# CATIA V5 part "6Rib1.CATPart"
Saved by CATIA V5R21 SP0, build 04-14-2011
Part number: Rib1
Bounding box of the stored display mesh (mm): x 12 to 22, y -42.784 to 24.466, z 44.139 to 68.639
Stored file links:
  C:\Users\水心\Desktop\Arm_Detailed_Design_Assembly_Manu\6Rib1.CATPart
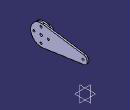
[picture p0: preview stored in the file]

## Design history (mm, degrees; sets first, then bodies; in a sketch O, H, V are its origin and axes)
Body1 (main body)
  DatumSurface1
  DatumSurface2
  Plane1 to Plane3: stored without definition
  Sketch1 on face of DatumSurface1, origin (22, 0, 0), H (0, 1, 0), V (0, 0, 1)
    projected circle E1 centre (-30.534, 56.389) radius 12.25 from edge of DatumSurface2
    projected arc E2 centre (-30.534, 56.389) radius 12.25 from (-28.7577, 68.5095) to (-28.7577, 44.2684) ccw from edge of DatumSurface2
    projected circle E3 centre (-30.534, 56.389) radius 1.5 from edge of DatumSurface2
    arc A1 centre (19.466, 56.389) radius 5 from (20.191, 51.4418) to (20.191, 61.3361) ccw
    point P1 (19.466, 56.389)
    reference intersected line E4 through (-30.534, 0) direction (0, 1) from Plane1
    line L1 (20.191, 61.3361) -> (-28.7577, 68.5095)
    axis line L2 (30.2795, 56.389) -> (-56.8378, 56.389)
    reference intersected line E5 through (0, 56.389) direction (1, 0) from Plane2
    line L3 (-28.7577, 44.2684) -> (20.191, 51.4418)
    point P4 (-28.7577, 44.2684)
    point P5 (-28.7577, 68.5095)
    point P8 (-28.7577, 68.5095)
    circle A2 centre (19.466, 56.389) radius 1.25
    circle A3 centre (-30.534, 64.889) radius 1.25
    point P9 (-30.534, 64.889)
    reference intersected line E6 through (0, 56.389) direction (-1, 0) from Plane3
    circle A4 centre (-39.034, 56.389) radius 1.25
    circle A5 centre (-30.534, 47.889) radius 1.25
    circle A6 centre (-22.034, 56.389) radius 1.25
    distance P1 E4 = 50
    radius A1 = 5
    radius A2 = 1.25
    radius A3 = 1.25
    distance E6 P9 = 8.5
    tangency: L1 E1, L1 A1, L3 A1, L3 E1
    horizontal: L2 H
    coincidence: P1 L2, L2 E5, E1 P4, E1 P5, L1 P8, P5 P8
  Pad1: profile Sketch1, direction (-1, 0, 0), length 2
Body2
  Sketch2 on end face of Pad1, origin (20, 0, 0), H (0, -1, 0), V (0, 0, 1)
    circle A1 centre (30.534, 56.389) radius 12.25
    point P1 (30.534, 56.389)
    reference projected arc E1 centre (30.534, 56.389) radius 12.25 from (28.7577, 44.2684) to (28.7577, 68.5095) ccw from edge [end face of Pad1 | face of Pad1 from Sketch1.E2]
    circle A2 centre (30.534, 64.889) radius 1.25
    point P2 (30.534, 64.889)
    circle A3 centre (39.034, 56.389) radius 1.25
    point P3 (39.034, 56.389)
    circle A4 centre (30.534, 47.889) radius 1.25
    point P4 (30.534, 47.889)
    circle A5 centre (22.034, 56.389) radius 1.25
    point P5 (22.034, 56.389)
    circle A6 centre (30.534, 56.389) radius 1.5
    radius A2 = 1.25
    radius A3 = 1.25
    radius A4 = 1.25
    radius A5 = 1.25
    distance P2 P1 = 8.5
    distance P3 P1 = 8.5
    distance P1 P4 = 8.5
    distance P5 P1 = 8.5
    radius A6 = 1.5
    coincidence: A1 E1
  Pad2: profile Sketch2, direction (-1, 0, 0), length 2
  Sketch3 on end face of Pad2, origin (18, 0, 0), H (0, -1, 0), V (0, 0, 1)
    circle A1 centre (30.534, 56.389) radius 1.5
    circle A2 centre (30.534, 56.389) radius 4
    reference projected circle E1 centre (30.534, 56.389) radius 1.5 from edge [end face of Pad2 | face of Pad2 from Sketch2.A6]
    radius A2 = 4
    coincidence: A1 E1
  Pocket1: profile Sketch3, direction (1, 0, 0), length 1
  Sketch4 on end face of Pad2, origin (18, 0, 0), H (0, -1, 0), V (0, 0, 1)
    circle A1 centre (30.534, 56.389) radius 6.1
    reference projected circle E1 centre (30.534, 56.389) radius 12.25 from edge [face of Pad2 from Sketch2.A1 | end face of Pad2]
    circle A2 centre (30.534, 56.389) radius 4
    radius A1 = 6.1
    radius A2 = 4
    concentricity: A1 E1
  Pad3: profile Sketch4, direction (-1, 0, 0), length 6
